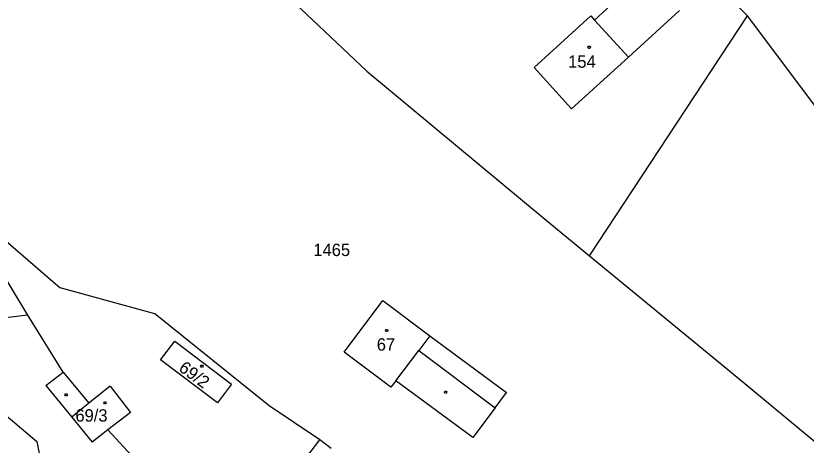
# Model space of a CAD drawing. Extents: x -850689 to -847910, y -1058374 to -1054747.
# Drawn here: x -849235.3 to -849126.6, y -1056154 to -1056094.9 of the extents above; entities that cross this region are included whole.
import ezdxf

# ---------------------------------------------------------------- set-up
doc = ezdxf.new("R2010")
doc.units = 0
for name, color, linetype in [('KN_HRANICE', 7, 'Continuous'), ('KN_KULTURY', 7, 'Continuous'), ('KN_PARCELY', 7, 'Continuous'), ('KN_SLUCKY', 7, 'Continuous'), ('KN_STAVEBNI', 7, 'Continuous')]:
    doc.layers.add(name, color=color, linetype=linetype)

# ---------------------------------------------------------------- blocks, each defined once
blk = doc.blocks.new('402')
blk.add_lwpolyline([(0.09, 0.15), (0.18, 0), (0.09, -0.15), (-0.09, -0.15), (-0.18, 0), (-0.09, 0.15), (0.09, 0.15)])

msp = doc.modelspace()

# ---------------------------------------------------------------- linework, layer by layer
at = {"layer": 'KN_HRANICE'}
for p, q in [((-849144.79, -1056084.84), (-849134.65, -1056094.95)), ((-849155.67, -1056095.51), (-849148.74, -1056089.13)), ((-849196.89, -1056093.18), (-849186.98, -1056102.56)), ((-849144.01, -1056094.18), (-849151.02, -1056100.61)), ((-849164, -1056102.05), (-849156.19, -1056094.94)), ((-849156.39, -1056127.95), (-849134.65, -1056094.95)), ((-849156.19, -1056094.94), (-849155.67, -1056095.51)), ((-849113.79, -1056122.8), (-849134.65, -1056094.95)), ((-849151.02, -1056100.61), (-849158.83, -1056107.72)), ((-849158.83, -1056107.72), (-849164, -1056102.05)), ((-849186.98, -1056102.56), (-849162.35, -1056123.05)), ((-849162.35, -1056123.05), (-849156.39, -1056127.95)), ((-849236.99, -1056125.61), (-849229.16, -1056132.38)), ((-849233.63, -1056136.15), (-849239.16, -1056126.97)), ((-849156.39, -1056127.95), (-849136.05, -1056144.68)), ((-849216.14, -1056135.95), (-849229.16, -1056132.38)), ((-849190.13, -1056141.21), (-849184.82, -1056134.14)), ((-849184.82, -1056134.14), (-849178.32, -1056138.97)), ((-849233.63, -1056136.15), (-849239.63, -1056136.86)), ((-849228.75, -1056143.99), (-849233.63, -1056136.15)), ((-849200.44, -1056148.6), (-849216.14, -1056135.95)), ((-849178.32, -1056138.97), (-849167.78, -1056146.8)), ((-849183.69, -1056146.04), (-849190.13, -1056141.21)), ((-849228.75, -1056143.99), (-849225.23, -1056148.27)), ((-849183.02, -1056145.16), (-849183.69, -1056146.04)), ((-849172.44, -1056152.99), (-849183.02, -1056145.16)), ((-849136.05, -1056144.68), (-849108.72, -1056167.41)), ((-849222.3, -1056145.89), (-849225.23, -1056148.27)), ((-849222.3, -1056145.89), (-849219.52, -1056149.53)), ((-849169.35, -1056148.89), (-849167.78, -1056146.8)), ((-849193.48, -1056153.3), (-849200.44, -1056148.6)), ((-849169.35, -1056148.89), (-849172.44, -1056152.99)), ((-849237.58, -1056149.18), (-849232.38, -1056153.52)), ((-849219.52, -1056149.53), (-849222.61, -1056151.92)), ((-849222.61, -1056151.92), (-849217.32, -1056157.67)), ((-849232.38, -1056153.52), (-849229.69, -1056167.78)), ((-849200.94, -1056163.12), (-849193.48, -1056153.3)), ((-849191.92, -1056154.48), (-849193.48, -1056153.3))]:
    msp.add_line(p, q, dxfattribs=at)
at = {"layer": 'KN_SLUCKY'}
for p, q in [((-849155.67, -1056095.51), (-849151.02, -1056100.61)), ((-849178.32, -1056138.97), (-849179.84, -1056141.02)), ((-849215.38, -1056142.29), (-849213.42, -1056139.7)), ((-849213.42, -1056139.7), (-849205.59, -1056145.62)), ((-849183.02, -1056145.16), (-849179.84, -1056141.02)), ((-849179.84, -1056141.02), (-849169.35, -1056148.89)), ((-849207.55, -1056148.21), (-849215.38, -1056142.29)), ((-849231.13, -1056145.84), (-849228.75, -1056143.99)), ((-849205.59, -1056145.62), (-849207.55, -1056148.21)), ((-849231.13, -1056145.84), (-849227.58, -1056150.18)), ((-849225.23, -1056148.27), (-849227.58, -1056150.18)), ((-849227.58, -1056150.18), (-849224.79, -1056153.6)), ((-849222.61, -1056151.92), (-849224.79, -1056153.6))]:
    msp.add_line(p, q, dxfattribs=at)
at = {"layer": 'KN_STAVEBNI'}
for p, q in [((-849164, -1056102.05), (-849156.19, -1056094.94)), ((-849156.19, -1056094.94), (-849155.67, -1056095.51)), ((-849155.67, -1056095.51), (-849151.02, -1056100.61)), ((-849151.02, -1056100.61), (-849158.83, -1056107.72)), ((-849158.83, -1056107.72), (-849164, -1056102.05)), ((-849190.13, -1056141.21), (-849184.82, -1056134.14)), ((-849184.82, -1056134.14), (-849178.32, -1056138.97)), ((-849178.32, -1056138.97), (-849179.84, -1056141.02)), ((-849215.38, -1056142.29), (-849213.42, -1056139.7)), ((-849213.42, -1056139.7), (-849205.59, -1056145.62)), ((-849183.69, -1056146.04), (-849190.13, -1056141.21)), ((-849183.02, -1056145.16), (-849179.84, -1056141.02)), ((-849207.55, -1056148.21), (-849215.38, -1056142.29)), ((-849205.59, -1056145.62), (-849207.55, -1056148.21)), ((-849183.02, -1056145.16), (-849183.69, -1056146.04)), ((-849222.3, -1056145.89), (-849225.23, -1056148.27)), ((-849222.3, -1056145.89), (-849219.52, -1056149.53)), ((-849225.23, -1056148.27), (-849227.58, -1056150.18)), ((-849219.52, -1056149.53), (-849222.61, -1056151.92)), ((-849227.58, -1056150.18), (-849224.79, -1056153.6)), ((-849222.61, -1056151.92), (-849224.79, -1056153.6))]:
    msp.add_line(p, q, dxfattribs=at)

# ---------------------------------------------------------------- block references
at = {"layer": 'KN_KULTURY'}
for p in [(-849156.42, -1056099.26), (-849184.27, -1056138.24), (-849209.7, -1056143.15), (-849176.16, -1056146.73), (-849228.36, -1056147.1), (-849223.01, -1056148.21)]:
    msp.add_blockref('402', p, dxfattribs=at)

# ---------------------------------------------------------------- texts
at = {"layer": 'KN_PARCELY'}
for s, p in [('154', (-849159.32, -1056102.08)), ('1465', (-849194.36, -1056128)), ('67', (-849185.63, -1056141.02)), ('69/3', (-849227.08, -1056150.79))]:
    msp.add_text(s, height=1.7, dxfattribs=at).set_placement(p)
msp.add_text('69/2', height=1.7, rotation=323.492, dxfattribs=at).set_placement((-849213, -1056143.69))

doc.saveas('drawing.dxf')
